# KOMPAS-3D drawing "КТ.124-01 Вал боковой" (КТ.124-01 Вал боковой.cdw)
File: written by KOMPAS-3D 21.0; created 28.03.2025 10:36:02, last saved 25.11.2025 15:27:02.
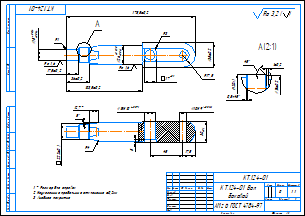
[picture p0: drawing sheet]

Sheet 1: A3, landscape

Document properties: Автор: User; Организация: Марсель; Полное имя файла: C:\Users\User\Desktop\Pelorus PRO доработки\ЗАФИКСИРОВАЛИ\Вал боковой\КТ.124-01 Вал боковой.cdw; Знак неуказанной шероховатости: 4; Параметр неуказанной шероховатости: Ra 3,2

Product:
- Part/product: КТ.124-01 Вал боковой
    Комментарий: Марсель

Title block, sheet 1: Наименование: КТ.124-01 Вал / боковой; designation: КТ.124-01; Материал: АМг 6 ГОСТ 4784-97; Масса: 0; Количество листов документа: 1; Форматы листов документа: A3; stored path: C:\Users\User\Downloads\Вал боковой _ КТ.124 (1).cdw

Views: Вид 1, Справа, Проекционный вид 2, Местный разрез 1, Выносной элемент 3, Выносной элемент А, Выносной элемент
Referenced files in D:\Marat\work\eholot\KazanTarget\детали\детали KT Pro 1\КТ.124 Вал боковой\: КТ.124 Вал боковой.m3d
Referenced files in C:\Users\User\Desktop\Pelorus PRO доработки\ЗАФИКСИРОВАЛИ\Вал боковой\: КТ.124-01 Вал боковой.m3d
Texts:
  Ra 1,6
  JS12
  Ra 3,2
  Ra 3,2 ( )
Dimensions and other numbers on the sheet: 36±0,2; 103,5±0,2; 26; 15; 1; 178,5±0,2; 35±0,2; 17,5±0,2; 17; 3; 45; 5; 30; 10; 22,2±0,1; 4; 12,7; 0,8; 18±0,2; 20; 1:1; 0

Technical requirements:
  * Размер для справок
  Неуказанные предельные отклонения ±0,2мм.
  Анодное покрытие.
